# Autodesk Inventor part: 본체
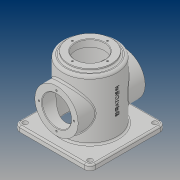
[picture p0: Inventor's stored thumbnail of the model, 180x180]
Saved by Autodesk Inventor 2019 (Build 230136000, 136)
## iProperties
Created: 2019-03
Part Number: 본체
Material: 일반
Document SubType Name: Modeling
Designer: PC312-17
Density: 1 g/cm^3
Appearance: 기본값
Author: PC312-17
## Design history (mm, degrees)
sketch "스케치1"
  geometry: C1 r 50 at (0, 0); 1 further point
  constraints: 1 centre point, 1 coincident
  dimensions: "d0" = 100 diameter of C1
extrude "돌출1" new body sketch "스케치1" distance "d1" = 120; taper "d2" = 0 deg
node "작업 평면1"
sketch "스케치4"
  geometry: C1 r 40 at (0, 60); 1 further point
  constraints: 1 centre point, 1 vertical alignment
  dimensions: "d10" = 80 diameter of C1; "d11" = 60 distance of point (0, 0) C1.centre
extrude "돌출4" join sketch "스케치4" stored distance "d12" = 112; taper "d13" = 0 deg
sketch "스케치5"
  geometry: C1 r 40 at (0, 0) reference; C2 r 27 at (0, 0); 1 further point
  constraints: 1 centre point, 1 coincident
  dimensions: "d14" = 54 diameter of C2
extrude "돌출5" cut sketch "스케치5" extent not by distance; stored distance "d15" = 112; taper "d16" = 0 deg
sketch "스케치6"
  geometry: L1 (70, 70)-(-70, 70); L2 (-70, 70)-(-70, -70); L3 (-70, -70)-(70, -70); L4 (70, -70)-(70, 70); L5 (70, 70)-(-70, -70); L6 (-70, 70)-(70, -70); C1 r 50 at (0, 0) reference; 1 further point
  constraints: 12 end point, 2 midpoint, 2 parallel, 1 horizontal, 1 perpendicular
  dimensions: "d17" = 140 distance of L3.end L2.end; "d18" = 140 distance of L2.end L1.end
extrude "돌출6" join sketch "스케치6" distance "d19" = 10; taper "d20" = 0 deg
sketch "스케치7"
  geometry: C1 r 27 at (0, 0) reference; C2 r 40 at (0, 0) reference; 2 further points
  constraints: 1 vertical alignment
  dimensions: "d21" = 32.5 distance of point (0, 32.5) C1.centre
hole "구멍1" sketch "스케치7" at (0, 32.5) diameter "d22" = 3.242; stored, may be unused: countersink angle "d26" = 90 deg, drill point angle "d28" = 118 deg; dims "d23" = 8, "d24" = 4, "d25" = 2, "d27" = 10
sketch "스케치8"
  geometry: C1 r 40 at (0, 0); 1 further point
  constraints: 1 centre point, 1 coincident
  dimensions: "d32" = 80 diameter of C1
extrude "돌출7" join sketch "스케치8" distance "d33" = 5; taper "d34" = 0 deg
sketch "스케치9"
  geometry: C1 r 27 at (0, 0); 1 further point
  constraints: 1 centre point, 1 coincident
  dimensions: "d35" = 54 diameter of C1
extrude "돌출8" cut sketch "스케치9" distance "d36" = 13; taper "d37" = 0 deg
sketch "스케치10"
  geometry: C1 r 45 at (0, 0); 1 further point
  constraints: 1 centre point, 1 coincident
  dimensions: "d38" = 90 diameter of C1
extrude "돌출9" cut sketch "스케치10" extent not by distance; stored distance "d39" = 13; taper "d40" = 0 deg
sketch "스케치11"
  geometry: 2 further points
  constraints: 1 vertical alignment
  dimensions: "d41" = 32.5 distance of point (0, 32.5) point (0, 0)
hole "구멍2" sketch "스케치11" at (0, 32.5) diameter "d42" = 3.242; stored, may be unused: countersink angle "d46" = 90 deg, drill point angle "d48" = 118 deg; dims "d43" = 8, "d44" = 4, "d45" = 2, "d47" = 10
fillet "모깎기1" dims "d52" = 10
sketch "스케치12"
  geometry: C1 r 4.5 at (60, 60); C2 r 4.5 at (-60, 60); C3 r 4.5 at (-60, -60); C4 r 4.5 at (60, -60); A1 r 10 centre (60, 60) between (70, 60) and (60, 70) reference; A2 r 10 centre (-60, 60) between (-60, 70) and (-70, 60) reference; A3 r 10 centre (-60, -60) between (-70, -60) and (-60, -70) reference; A4 r 10 centre (60, -60) between (60, -70) and (70, -60) reference; 1 further point
  constraints: 4 centre point, 4 coincident
  dimensions: "d53" = 9 diameter of C1; "d54" = 9 diameter of C2; "d55" = 9 diameter of C3; "d56" = 9 diameter of C4
extrude "돌출10" cut sketch "스케치12" distance "d57" = 13; taper "d58" = 0 deg
chamfer "모따기1" distance "d59" = 1; stored, may be unused: second distance "d60" = 2, angle "d61" = 45 deg
fillet "모깎기2" dims "d62" = 3
fillet "모깎기3" dims "d63" = 3
fillet "모깎기4" dims "d64" = 5
fillet "모깎기5" dims "d65" = 3
fillet "모깎기6" dims "d66" = 3
fillet "모깎기7" dims "d67" = 3
fillet "모깎기8" dims "d68" = 3
node "작업 평면2"
sketch "스케치14"
  geometry: L1 (0, -60)-(0, 60) reference; 3 further points
  constraints: 1 horizontal alignment, 1 midpoint, 1 other
  dimensions: "d70" = 70 distance of point (0, 0) point (70, 0)
feature "엠보싱1" sketch "스케치14" dims "d1" = 120, "d71" = 0.5, "d72" = 0
node "솔리드1"
mirror "미러1"
pattern_circular "원형 패턴1" dims angle "d30" = 360 deg
mirror "미러2"
pattern_circular "원형 패턴2" dims angle "d50" = 360 deg
node "투영된 루프1"
node "투영된 루프2"
other parameters: "d9" = 62
